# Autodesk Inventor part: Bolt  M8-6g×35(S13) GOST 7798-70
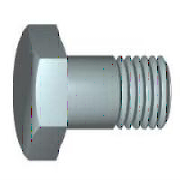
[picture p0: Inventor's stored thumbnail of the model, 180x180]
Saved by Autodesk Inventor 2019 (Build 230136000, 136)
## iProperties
Created: 2018-01
Part Number: Bolt  M8-6g×35(S13) GOST 7798-70
Material: Steel, Mild
Description: Hexagon bolts, product grade B
Document SubType Name: Modeling
Standard: GOST 7798-70
Designer: m.vorobev
Standards Organization: GOST
Language: en-US
Size Designation: M8-6g×35(S13)
Categories: <MemberInstance><Categories><Category DisplayName="Fasteners" InternalName="e4da775c-781d-43d5-af7c-5136215cf5a6" Mnemonic="FSTN"><Category DisplayName="Bolts"
Mass: 4.46121 g
Surface Area: 4.48844 cm^2
Volume: 0.567584 cm^3
Density: 7.85 g/cm^3
Appearance: Semi-Polished
IsCustomPart: 0
Title: Bolt
Author: m.vorobev
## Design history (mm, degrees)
sketch "Sketch1"
  geometry: L1 (0, 0)-(6.175, 0); L2 (9.75, -2.064)-(9.75, -5.3); L3 (9.75, -5.3)-(4, -5.3); L4 (4, -5.3)-(4, -40.3); L5 (4, -40.3)-(0, -40.3); L6 (0, -40.3)-(0, 0); L7 (6.175, 0)-(9.75, -2.064)
  constraints: 14 end point, 4 parallel, 1 horizontal, 1 perpendicular
  dimensions: "d0" = 19.5 diameter of L2 L6 (= 1.5 x S_); "d1" = 8 diameter of L4 L6 (= d1_); "d2" = 5.3 distance between parallel lines of L1 L3 (= k); "d3" = 35 distance between parallel lines of L3 L5 (= L); "d20" = 30 deg angle of L1 L7; "d21" = 12.35 diameter of L1.end L6 (= 0.95 x S_)
revolve "Revolution1" sketch "Sketch1" stored, may be unused: angle "d4" = 90 deg
thread "Thread1" dims "d12" = 22 (= b), "d13" = 0
chamfer "Chamfer1" distance "d14" = 0.66667 (= 0.0833333 x d); stored, may be unused: second distance "d15" = 2, angle "d16" = 45 deg
body "Solid1"
sketch "Sketch2"
  geometry: L1 (0, -7.506)-(-6.5, -3.753); L2 (-6.5, -3.753)-(-6.5, 3.753); L3 (-6.5, 3.753)-(0, 7.506); L4 (0, 7.506)-(6.5, 3.753); L5 (6.5, 3.753)-(6.5, -3.753); L6 (6.5, -3.753)-(0, -7.506); C1 r 9.75 at (0, 0) reference; 2 further points
  constraints: 12 end point, 1 coincident, 1 vertical alignment, 13 other
  dimensions: "d22" = 13 distance between parallel lines of L5 L2 (= S_)
extrude "Extrusion1" cut sketch "Sketch2" distance "d23" = 5.3 (= k); taper "d24" = 0 deg
other parameters: "d" = 8 [user parameter; used in 1 equation term], "d1_" = 8 [user parameter; used in 1 equation term], "S_" = 13 [user parameter; used in 3 equation terms], "k" = 5.3 [user parameter; used in 2 equation terms], "e" = 14.2 [user parameter], "L" = 35 [user parameter; used in 1 equation term], "b" = 22 [user parameter; used in 1 equation term], "Grip_Length" = 13 [user parameter], "d17" = 0, "d18" = 0, "d19" = 0
